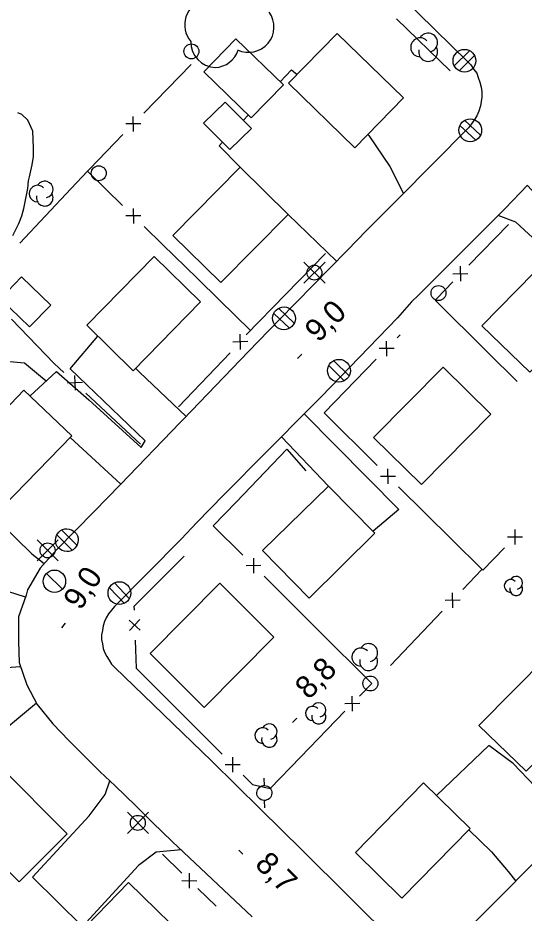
# Model space of a CAD drawing. Extents: x 381879 to 384696, y 5564785 to 5567594.
# Drawn here: x 383086.9 to 383154.5, y 5565538.7 to 5565658.4 of the extents above; entities that cross this region are included whole.
import ezdxf

# ---------------------------------------------------------------- set-up
doc = ezdxf.new("R2010")
doc.units = 0
for name, color, linetype in [('Niveau 19', 7, 'Continuous'), ('Niveau 2', 7, 'Continuous'), ('Niveau 21', 7, 'Continuous'), ('Niveau 22', 7, 'Continuous'), ('Niveau 3', 7, 'Continuous'), ('Niveau 31', 7, 'Continuous'), ('Niveau 36', 7, 'Continuous'), ('Niveau 37', 7, 'Continuous'), ('Niveau 44', 7, 'Continuous')]:
    doc.layers.add(name, color=color, linetype=linetype)

msp = doc.modelspace()

# ---------------------------------------------------------------- linework, layer by layer
at = {"layer": 'Niveau 19'}
for points in [[(383121.95, 5565649.84), (383123.47, 5565651.43), (383124.2, 5565650.81)], [(383117.02, 5565644.68), (383117.69, 5565645.38)], [(383133.65, 5565642.78), (383133.79, 5565642.67), (383136.58, 5565638.51), (383138.41, 5565634.92)], [(383116.6, 5565638.4), (383113.78, 5565641.28), (383114.24, 5565641.76)], [(383154.98, 5565635.98), (383160.39, 5565630.07), (383159.86, 5565629.64), (383166.18, 5565623.33), (383164.39, 5565621.68), (383158.8, 5565627.19), (383158.2, 5565626.7), (383155.09, 5565629.5), (383153.4, 5565631.09), (383151.08, 5565631.98)], [(383129.48, 5565625.85), (383123, 5565632.1)], [(383088.52, 5565607.82), (383092.06, 5565611.12), (383096.4, 5565607.33), (383103.36, 5565600.95), (383103.93, 5565601.84), (383093.9, 5565611.46), (383097.59, 5565615.84)], [(383102.64, 5565611.54), (383103.15, 5565611.02), (383109.38, 5565605.1)], [(383125.16, 5565605.45), (383137.78, 5565592.66), (383134.35, 5565589.76)], [(383100.64, 5565596.05), (383093.89, 5565602.28)], [(383128.4, 5565595.8), (383122.1, 5565602.37)], [(383090.41, 5565585.38), (383088.79, 5565586.7)], [(383087.91, 5565580.95), (383077.34, 5565584.33)], [(383078.43, 5565565.36), (383079.25, 5565567.78), (383082.99, 5565570.67), (383085.4, 5565571.55), (383087.27, 5565571.69)], [(383089.4, 5565566.79), (383084.03, 5565562.31), (383076.8, 5565555.33), (383072.08, 5565550.36), (383068.41, 5565554.6), (383070.1, 5565556.4)], [(383160.83, 5565550.53), (383155.98, 5565555.67), (383153.07, 5565558.72), (383149.83, 5565561.11), (383142.81, 5565554.41)], [(383108.7, 5565547.17), (383105.36, 5565546.87), (383103.04, 5565545.05), (383095.53, 5565536.91), (383088.88, 5565543.49), (383096.42, 5565551.72), (383098.58, 5565554.57), (383099.18, 5565556.38)], [(383147.13, 5565549.83), (383150.18, 5565546.89), (383152.39, 5565544.29), (383153.41, 5565542.98)]]:
    msp.add_lwpolyline(points, dxfattribs=at)
at = {"layer": 'Niveau 2'}
msp.add_lwpolyline([(383086.24, 5565629.3), (383087.02, 5565630.87), (383087.44, 5565631.91), (383087.72, 5565632.9), (383087.91, 5565633.99), (383088.24, 5565635.57), (383088.31, 5565636.61), (383088.45, 5565637.11), (383088.83, 5565638.74), (383089.01, 5565639.87), (383089.01, 5565641.01), (383088.9, 5565643.22), (383088.7, 5565643.74), (383088.24, 5565644.72), (383087.45, 5565645.48), (383086.9, 5565645.67)], dxfattribs=at)
at = {"layer": 'Niveau 21'}
for points in [[(383107.9, 5565690.4), (383121.1, 5565677.6), (383138.2, 5565661.2), (383147, 5565652.5)], [(383147, 5565652.5), (383147.4, 5565652.1), (383147.8, 5565651.5), (383148.2, 5565651), (383148.4, 5565650.4), (383148.6, 5565649.8), (383148.8, 5565649.1), (383148.9, 5565648.5), (383148.9, 5565647.8), (383148.8, 5565647.2), (383148.7, 5565646.6), (383148.5, 5565645.9), (383148.2, 5565645.3), (383147.9, 5565644.8), (383147.5, 5565644.2), (383147.1, 5565643.7)], [(383147.1, 5565643.7), (383137.7, 5565634.2)], [(383155, 5565636), (383152, 5565632.9)], [(383137.7, 5565634.2), (383134.8, 5565631.3), (383133.5, 5565630)], [(383152, 5565632.9), (383140.4, 5565621.3), (383139.5, 5565620.4)], [(383133.5, 5565630), (383130.9, 5565627.3)], [(383130.9, 5565627.3), (383121.8, 5565618), (383117.7, 5565613.8)], [(383139.5, 5565620.4), (383137.6, 5565618.3)], [(383137.6, 5565618.3), (383127.4, 5565607.7), (383125.9, 5565606.2)], [(383117.7, 5565613.8), (383109, 5565604.7)], [(383125.9, 5565606.2), (383114.4, 5565594.6), (383110.8, 5565590.9)], [(383109, 5565604.7), (383108.6, 5565604.3), (383100.6, 5565596)], [(383100.6, 5565596), (383097.1, 5565592.4), (383092.1, 5565587.3), (383089.9, 5565584.8)], [(383110.8, 5565590.9), (383108.7, 5565588.7)], [(383108.7, 5565588.7), (383099.8, 5565579.7)], [(383089.9, 5565584.8), (383088.2, 5565581.9), (383088, 5565581.2)], [(383088, 5565581.2), (383087, 5565578.3), (383087, 5565575), (383087.1, 5565572.2), (383088.1, 5565569.2)], [(383099.8, 5565579.7), (383099.4, 5565579.2), (383099, 5565578.7), (383098.7, 5565578.2), (383098.5, 5565577.7), (383098.3, 5565577.1), (383098.2, 5565576.5), (383098.1, 5565575.9), (383098.1, 5565575.3), (383098.2, 5565574.7), (383098.3, 5565574.1), (383098.5, 5565573.6), (383098.8, 5565573), (383099.1, 5565572.5), (383099.4, 5565572), (383099.8, 5565571.6)], [(383099.8, 5565571.6), (383112.8, 5565559), (383119.3, 5565552.6)], [(383088.1, 5565569.2), (383089.5, 5565566.6), (383091.6, 5565564), (383093.7, 5565561.8), (383097.9, 5565557.6)], [(383097.9, 5565557.6), (383099.9, 5565555.7)], [(383099.9, 5565555.7), (383102.6, 5565553.1)], [(383102.6, 5565553.1), (383104.9, 5565550.8), (383107.5, 5565548.3)], [(383119.3, 5565552.6), (383124.9, 5565547.1), (383137.4, 5565534.7)], [(383145.2, 5565534.7), (383156.2, 5565545.8), (383160.9, 5565550.6)], [(383107.5, 5565548.3), (383118.2, 5565538.2)]]:
    msp.add_lwpolyline(points, dxfattribs=at)
at = {"layer": 'Niveau 22'}
msp.add_lwpolyline([(383036.05, 5565584.2), (383044.34, 5565588.91), (383053.27, 5565596.08), (383062.54, 5565605.5), (383067.76, 5565608.95), (383068.36, 5565609.34), (383076.46, 5565611.48), (383082.91, 5565612.7), (383087.81, 5565612.27), (383090.21, 5565610.25), (383090.69, 5565609.85)], dxfattribs=at)
at = {"layer": 'Niveau 3'}
for p, q in [((383124.27, 5565612.84), (383124.84, 5565613.41)), ((383092.79, 5565576.82), (383093.28, 5565577.46)), ((383123.59, 5565564.18), (383124.16, 5565564.75)), ((383116.4, 5565547.13), (383116.97, 5565546.58))]:
    msp.add_line(p, q, dxfattribs=at)
at = {"layer": 'Niveau 31'}
for points in [[(383118.09, 5565645), (383111.73, 5565651.16), (383116.02, 5565655.59), (383122.38, 5565649.43)], [(383129.57, 5565656.31), (383138.43, 5565647.67), (383131.92, 5565641.01), (383123.06, 5565649.65)], [(383115.2, 5565640.8), (383118.1, 5565643.6), (383114.6, 5565647.1), (383111.7, 5565644.3)], [(383123, 5565632.1), (383116.6, 5565638.4), (383107.6, 5565629.3), (383114, 5565623)], [(383111.3, 5565620.4), (383105.1, 5565626.5), (383096.1, 5565617.3), (383102.3, 5565611.2)], [(383155.3, 5565611), (383148.9, 5565617.2), (383158.2, 5565626.7), (383164.6, 5565620.5)], [(383088.47, 5565617.07), (383084.58, 5565620.83), (383087.4, 5565623.74), (383091.29, 5565619.98)], [(383140.8, 5565596), (383134.4, 5565602.3), (383143.7, 5565611.7), (383150.1, 5565605.4)], [(383094.1, 5565602.5), (383087.7, 5565608.6), (383078.7, 5565599.2), (383085, 5565593.1)], [(383125.8, 5565580.8), (383119.6, 5565587.2), (383128.4, 5565595.8), (383134.6, 5565589.5)], [(383111.8, 5565566.2), (383104.6, 5565573.4), (383113.9, 5565582.8), (383121.1, 5565575.6)], [(383163.9, 5565567), (383157.7, 5565573.1), (383148.5, 5565563.8), (383154.8, 5565557.7)], [(383078, 5565552), (383084.4, 5565558.4), (383093.5, 5565549.3), (383087.1, 5565542.9)], [(383147.3, 5565550), (383141.1, 5565556.1), (383132, 5565546.8), (383138.2, 5565540.7)], [(383094.7, 5565535.6), (383101.7, 5565542.8), (383111, 5565533.7), (383104, 5565526.5)]]:
    msp.add_lwpolyline(points, close=True, dxfattribs=at)
at = {"layer": 'Niveau 36'}
for p, q in [((383147.25, 5565653.99), (383145.19, 5565651.95)), ((383145.85, 5565651.31), (383147.91, 5565653.35)), ((383148.7, 5565642.72), (383146.57, 5565644.69)), ((383145.96, 5565644), (383148.09, 5565642.03)), ((383127.94, 5565625.73), (383125.12, 5565622.91)), ((383127.94, 5565622.91), (383125.12, 5565625.73)), ((383123.81, 5565617.56), (383121.71, 5565619.56)), ((383121.09, 5565618.88), (383123.19, 5565616.88)), ((383131.15, 5565610.51), (383129.09, 5565612.55)), ((383128.45, 5565611.89), (383130.51, 5565609.85)), ((383094.79, 5565587.88), (383092.74, 5565589.93)), ((383092.29, 5565588.61), (383089.47, 5565585.79)), ((383092.29, 5565585.79), (383089.47, 5565588.61)), ((383092.11, 5565589.26), (383094.16, 5565587.21)), ((383092.86, 5565582), (383090.74, 5565584.12)), ((383101.79, 5565580.75), (383099.8, 5565582.86)), ((383099.15, 5565582.21), (383101.14, 5565580.1)), ((383119.75, 5565556.76), (383119.8, 5565555.76)), ((383119.9, 5565552.76), (383119.86, 5565553.76)), ((383104.35, 5565552.18), (383101.53, 5565549.36)), ((383104.35, 5565549.36), (383101.53, 5565552.18))]:
    msp.add_line(p, q, dxfattribs=at)
for centre, radius in [((383110.09, 5565653.9), 1), ((383146.56, 5565652.65), 1.52), ((383097.71, 5565637.61), 1), ((383126.52, 5565624.32), 1), ((383143.09, 5565621.6), 1), ((383090.87, 5565587.2), 1), ((383091.79, 5565583.06), 1.5), ((383133.99, 5565569.4), 1), ((383102.93, 5565550.77), 1)]:
    msp.add_circle(centre, radius, dxfattribs=at)
for centre, major_axis, ratio in [((383147.33, 5565643.35), (0.01, 1.52), 0.999981), ((383122.45, 5565618.21), (0.02, 1.52), 0.999984), ((383129.8, 5565611.21), (-0.01, -1.52), 0.999981), ((383093.45, 5565588.56), (0.02, 1.52), 0.999984), ((383100.47, 5565581.49), (0.01, 1.52), 0.999983), ((383119.83, 5565554.77), (-0.05, -0.999), 0.999983)]:
    msp.add_ellipse(centre, major_axis=major_axis, ratio=ratio, dxfattribs=at)
at = {"layer": 'Niveau 37'}
for p, q in [((383102.35, 5565643.21), (383102.32, 5565645.21)), ((383103.34, 5565644.23), (383101.34, 5565644.2)), ((383102.32, 5565632.91), (383102.34, 5565630.91)), ((383103.33, 5565631.92), (383101.33, 5565631.9)), ((383145.98, 5565625.19), (383146.01, 5565623.18)), ((383145, 5565624.17), (383147, 5565624.2)), ((383116.66, 5565614.07), (383116.6, 5565616.08)), ((383117.63, 5565615.1), (383115.63, 5565615.05)), ((383136.19, 5565613.17), (383136.16, 5565615.18)), ((383137.17, 5565614.19), (383135.17, 5565614.16)), ((383094.49, 5565610.59), (383094.55, 5565608.59)), ((383095.52, 5565609.62), (383093.52, 5565609.56)), ((383136.35, 5565596.11), (383136.34, 5565598.11)), ((383135.34, 5565597.11), (383137.34, 5565597.12)), ((383153.33, 5565587.97), (383153.31, 5565589.97)), ((383154.32, 5565588.98), (383152.32, 5565588.96)), ((383118.37, 5565586.15), (383118.38, 5565584.15)), ((383119.38, 5565585.16), (383117.38, 5565585.14)), ((383145, 5565579.5), (383144.95, 5565581.5)), ((383145.98, 5565580.52), (383143.97, 5565580.48)), ((383101.77, 5565577.88), (383103.23, 5565576.52)), ((383101.82, 5565576.47), (383103.18, 5565577.94)), ((383131.6, 5565565.69), (383131.57, 5565567.69)), ((383132.58, 5565566.71), (383130.58, 5565566.68)), ((383114.6, 5565558.55), (383116.61, 5565558.55)), ((383115.61, 5565557.54), (383115.61, 5565559.55)), ((383108.82, 5565543.05), (383110.83, 5565543.04)), ((383109.82, 5565542.04), (383109.83, 5565544.05))]:
    msp.add_line(p, q, dxfattribs=at)
for points in [[(383144.66, 5565651.29), (383137.49, 5565658.26)], [(383103.73, 5565645.65), (383110.04, 5565652.14)], [(383094.03, 5565635.56), (383096.21, 5565637.89), (383096.52, 5565638.22), (383100.95, 5565642.78)], [(383100.9, 5565633.31), (383096.44, 5565637.67), (383096.43, 5565637.68), (383096.42, 5565637.68), (383096.21, 5565637.89)], [(383087.19, 5565628.25), (383094.03, 5565635.56)], [(383110.9, 5565623.52), (383106.22, 5565628.1), (383103.76, 5565630.51)], [(383152.42, 5565630.77), (383147.14, 5565625.31)], [(383117.39, 5565616), (383127.98, 5565626.88)], [(383117.98, 5565616.6), (383113.83, 5565620.65), (383110.9, 5565623.52)], [(383145.02, 5565623.11), (383142.86, 5565620.88)], [(383142.86, 5565620.88), (383142.64, 5565620.66), (383149.69, 5565613.66)], [(383093.06, 5565610.96), (383091.76, 5565612.18), (383086.06, 5565618.09)], [(383137.56, 5565615.61), (383137.97, 5565616.03)], [(383108.37, 5565606.37), (383115.25, 5565613.62)], [(383149.69, 5565613.66), (383153.62, 5565609.77)], [(383127.82, 5565605.56), (383134.78, 5565612.74)], [(383103.27, 5565601.38), (383095.98, 5565608.22)], [(383127.82, 5565605.56), (383134.92, 5565598.52)], [(383116.08, 5565593.66), (383122.85, 5565600.71), (383125.39, 5565597.83)], [(383137.76, 5565595.7), (383144.86, 5565588.66)], [(383088.89, 5565586.61), (383081.74, 5565593.6)], [(383116.95, 5565586.56), (383113, 5565590.46), (383116.08, 5565593.66)], [(383144.86, 5565588.66), (383148.92, 5565584.64), (383149, 5565584.56), (383151.92, 5565587.54)], [(383109.11, 5565586.44), (383102.41, 5565579.69), (383102.43, 5565579.2)], [(383126.88, 5565576.68), (383119.79, 5565583.74)], [(383146.36, 5565581.95), (383148.9, 5565584.62), (383148.92, 5565584.64)], [(383136.7, 5565571.81), (383143.6, 5565579.05)], [(383134.19, 5565569.4), (383126.88, 5565576.68)], [(383102.57, 5565575.2), (383102.71, 5565571.45), (383107.12, 5565567.03)], [(383132.55, 5565567.7), (383134.19, 5565569.4)], [(383107.12, 5565567.03), (383114.19, 5565559.96)], [(383124.68, 5565559.57), (383130.59, 5565565.68)], [(383117.02, 5565557.13), (383118.26, 5565555.89), (383120.62, 5565555.38), (383124.68, 5565559.57)], [(383106.21, 5565546.58), (383108.82, 5565544.06)], [(383110.95, 5565541.99), (383113.4, 5565539.63)]]:
    msp.add_lwpolyline(points, dxfattribs=at)
at = {"layer": 'Niveau 44'}
for centre, radius, start, end in [((383140.63, 5565654.45), 1.26, 44.1153, 269.8039), ((383141.71, 5565655.08), 1.26, 282.2692, 149.7262), ((383141.71, 5565653.82), 1.26, 166.9368, 29.6212), ((383090.5, 5565635.44), 1.11, 282.2692, 149.7262), ((383089.54, 5565634.89), 1.11, 44.1153, 269.8039), ((383090.5, 5565634.33), 1.11, 166.9368, 29.6212), ((383153.47, 5565582.86), 0.855, 282.2692, 149.7262), ((383152.73, 5565582.44), 0.855, 44.1153, 269.8039), ((383153.47, 5565582.01), 0.855, 166.9368, 29.6212), ((383132.73, 5565572.93), 1.2, 44.1153, 269.8039), ((383133.76, 5565573.53), 1.2, 282.2692, 149.7262), ((383133.76, 5565572.33), 1.2, 166.9368, 29.6212), ((383126.28, 5565565.4), 0.949, 44.1153, 269.8039), ((383127.1, 5565565.87), 0.949, 282.2692, 149.7262), ((383127.1, 5565564.93), 0.949, 166.9368, 29.6212), ((383119.6, 5565562.44), 1.04, 44.1153, 269.8039), ((383120.49, 5565562.96), 1.04, 282.2692, 149.7262), ((383120.49, 5565561.93), 1.04, 166.9368, 29.6212)]:
    msp.add_arc(centre, radius, start, end, dxfattribs=at)
for centre, major_axis, ratio, start_param, end_param in [((383112.59, 5565657.44), (1.2, -3.19), 0.999627, 3.002964, 5.058761), ((383117.71, 5565657.17), (3.03, -1.57), 0.994853, 4.748322, 7.378958), ((383113.41, 5565655.14), (3.39, 0.39), 0.999627, 3.002964, 4.567228), ((383113.09, 5565655.15), (3.26, 1.03), 0.999612, 4.468555, 5.655963)]:
    msp.add_ellipse(centre, major_axis=major_axis, ratio=ratio, start_param=start_param, end_param=end_param, dxfattribs=at)

# ---------------------------------------------------------------- texts
at = {"layer": 'Niveau 3'}
for s, rotation, p in [('9,0  ', 44.7717, (383127.05, 5565614.88)), ('9,0  ', 57.0066, (383095.29, 5565579.06)), ('8,8  ', 44.7717, (383125.74, 5565567.14)), ('8,7  ', 314.8206, (383118.43, 5565545.09))]:
    msp.add_text(s, height=3, rotation=rotation, dxfattribs=at).set_placement(p)

doc.saveas('drawing.dxf')
